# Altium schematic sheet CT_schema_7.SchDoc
size 278 x 170 mm
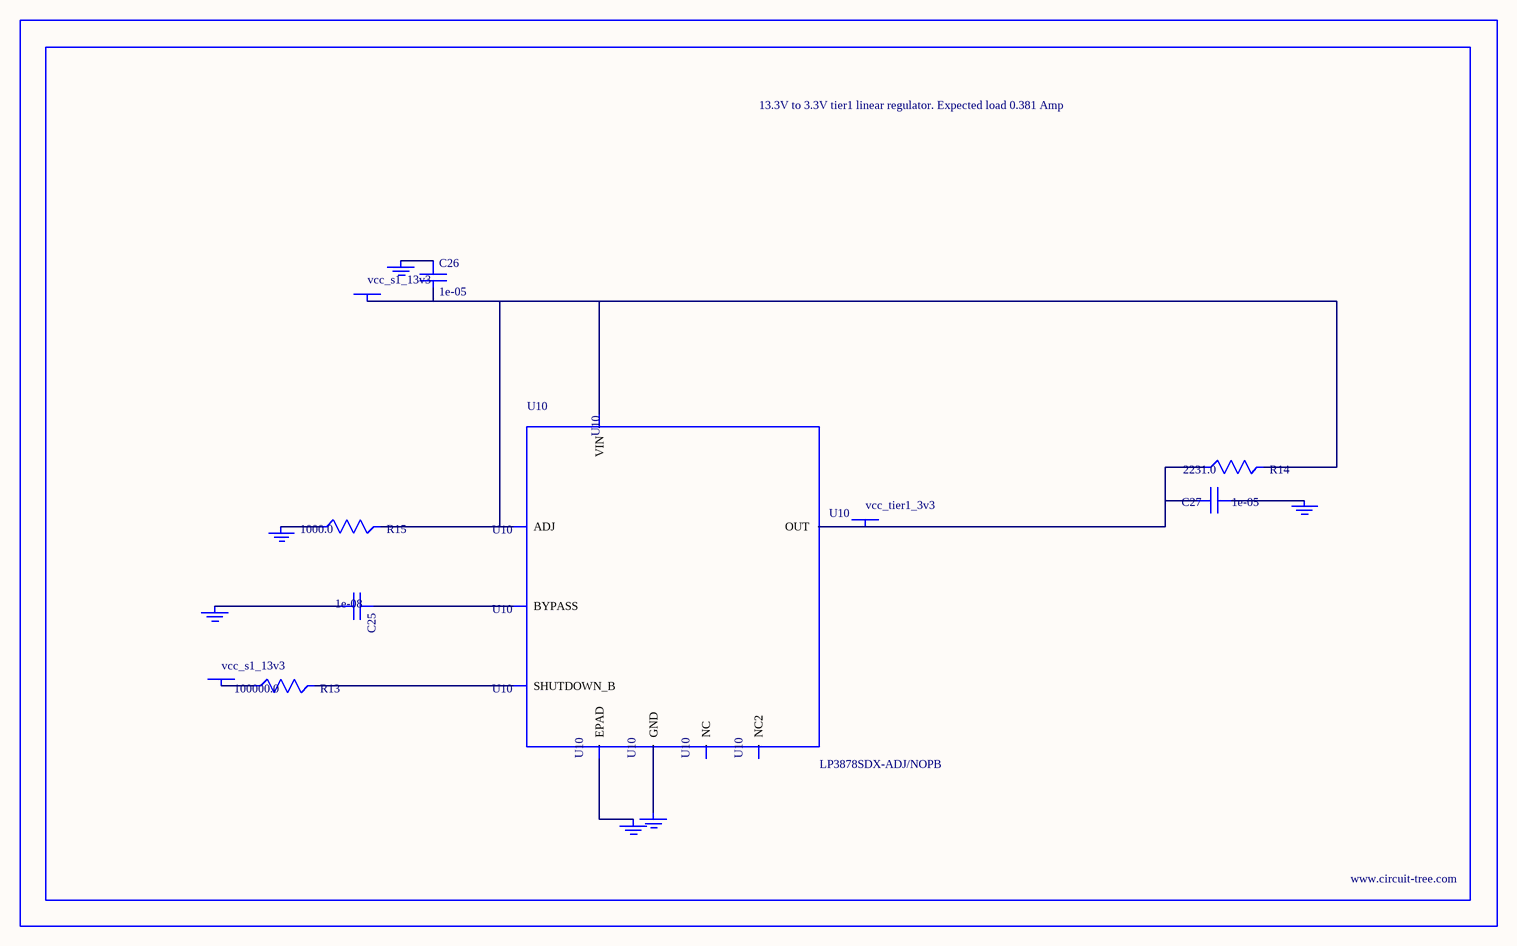
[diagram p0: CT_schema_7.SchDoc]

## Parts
BORDER6  (no value)
C25  1e-08  [C0402]
C26  1e-05  [C1210]
C27  1e-05  [C1210]
GND_INSTANCE_6_0  (no value)
GND_INSTANCE_6_1  (no value)
GND_INSTANCE_6_2  (no value)
GND_INSTANCE_6_3  (no value)
GND_INSTANCE_6_4  (no value)
GND_INSTANCE_6_5  (no value)
POWER_INSTANCE_6_0  vcc_s1_13v3
POWER_INSTANCE_6_1  vcc_s1_13v3
POWER_INSTANCE_6_2  vcc_tier1_3v3
R13  100000.0  [R0603]
R14  2231.0  [R0603]
R15  1000.0  [R0603]
U10  LP3878SDX-ADJ/NOPB  [WSON-8]

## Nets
NetC25_1: C25.1 U10.1(BYPASS)
NetC25_2: C25.2 GND_INSTANCE_6_0.0(GND)
NetC26_1: C26.1 GND_INSTANCE_6_1.0(GND)
NetC26_2: C26.2 POWER_INSTANCE_6_0.0(PWR) R14.2 R15.2 U10.4(VIN) U10.6(ADJ)
NetC27_1: C27.1 GND_INSTANCE_6_2.0(GND)
NetC27_2: C27.2 POWER_INSTANCE_6_2.0(PWR) R14.1 U10.5(OUT)
NetGND_INSTANCE_6_3_0: GND_INSTANCE_6_3.0(GND) R15.1
NetGND_INSTANCE_6_4_0: GND_INSTANCE_6_4.0(GND) U10.PAD(EPAD)
NetGND_INSTANCE_6_5_0: GND_INSTANCE_6_5.0(GND) U10.3(GND)
NetPOWER_INSTANCE_6_1_0: POWER_INSTANCE_6_1.0(PWR) R13.1
NetR13_2: R13.2 U10.8(SHUTDOWN_B)

Not connected (* = marked no-connect by the designer): U10 2(NC) 7(NC2)

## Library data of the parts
BORDER6 = BORDER_PAGE6
C25 = C0402C103K3RAC
C26 = C1210C106K5PACTU
C27 = GRM32DR61E106MA12L
GND_INSTANCE_6_0-GND_INSTANCE_6_5 = GND
POWER_INSTANCE_6_0-POWER_INSTANCE_6_2 = PWR
R13 = RC0603JR-07100KL
R14 = R14
R15 = RC0603JR-071KL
